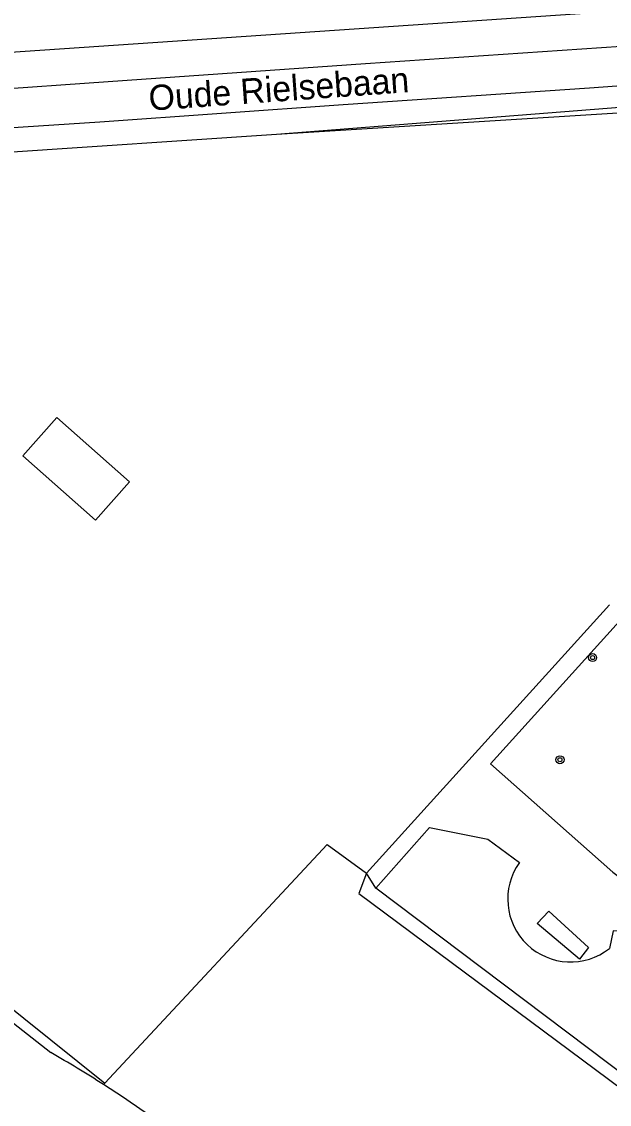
# Model space of a CAD drawing. Extents: x 126000 to 131009, y 393000 to 395500.
# Drawn here: x 130276.9 to 130335, y 394453.7 to 394560.9 of the extents above; entities that cross this region are included whole.
import ezdxf

# ---------------------------------------------------------------- set-up
doc = ezdxf.new("R2010")
doc.units = 0
for name, color, linetype in [('gg-afsc-faunaraster', 7, 'Continuous'), ('gg-anno-openbare ruimte label', 7, 'Continuous'), ('gg-bbg-bijgebouw', 7, 'Continuous'), ('gg-knt-onverhard', 7, 'Continuous'), ('gg-knt-verharding', 7, 'Continuous'), ('gg-kntw-bovenkant insteek waterloop', 7, 'Continuous'), ('gg-kntw-greppel-droge sloot', 7, 'Continuous'), ('gt-grn-groengrens', 7, 'Continuous'), ('gt-grn-groengrens NZ', 7, 'Continuous'), ('gt-grn-vlakafsluiter', 7, 'Continuous'), ('gt-symb-boom', 7, 'Continuous')]:
    doc.layers.add(name, color=color, linetype=linetype)

# ---------------------------------------------------------------- blocks, each defined once
blk = doc.blocks.new('gt0-BOOM')
at = {"layer": 'gt-symb-boom'}
for radius in [0.4, 0.2]:
    blk.add_circle((0, 0), radius, dxfattribs=at)

msp = doc.modelspace()

# ---------------------------------------------------------------- linework, layer by layer
at = {"layer": 'gg-afsc-faunaraster'}
for p, q in [((130378.68, 394554.51), (130302.11, 394549.74)), ((130302.11, 394549.74), (130187.63, 394542.05)), ((130335.05, 394503.16), (130311.01, 394476.57))]:
    msp.add_line(p, q, dxfattribs=at)
for points in [[(130187.63, 394542.05), (130185.82, 394540.52), (130184.79, 394538.46), (130185.47, 394536.26), (130247.98, 394485.55), (130285.09, 394455.78)], [(130285.09, 394455.78), (130307.12, 394479.42), (130311.01, 394476.57)]]:
    msp.add_lwpolyline(points, dxfattribs=at)
at = {"layer": 'gg-bbg-bijgebouw'}
msp.add_lwpolyline([(130280.36, 394521.7), (130276.99, 394517.91), (130284.19, 394511.54), (130287.55, 394515.33), (130280.36, 394521.7)], dxfattribs=at)
at = {"layer": 'gg-knt-onverhard'}
msp.add_lwpolyline([(130279.76, 394458.8), (130246.34, 394485.04), (130229.52, 394498.81), (130213, 394512.65), (130195.84, 394526.59), (130185.5, 394534.84)], dxfattribs=at)
for centre, radius, start, end in [((130220.06, 394354.36), 120.3, 57.3494, 60.2485), ((130219.87, 394354.03), 120.68, 45.3581, 57.3592)]:
    msp.add_arc(centre, radius, start, end, dxfattribs=at)
at = {"layer": 'gg-knt-verharding'}
for points in [[(130424.91, 394564.57), (130411.07, 394563.63), (130385.63, 394561.94), (130361, 394560.25), (130336.23, 394558.45), (130310.9, 394556.74), (130285.45, 394554.95), (130261.04, 394553.24), (130235.64, 394551.46), (130210.72, 394549.8), (130185.37, 394547.93), (130176.1, 394547.26)], [(130427.7, 394560.88), (130404.94, 394559.22), (130380.98, 394557.68), (130357.04, 394556.06), (130333.1, 394554.32), (130308.71, 394552.68), (130284.61, 394550.97), (130273.95, 394550.25), (130249.48, 394548.47), (130223.83, 394546.74), (130199.17, 394544.98), (130191.11, 394544.42)]]:
    msp.add_lwpolyline(points, dxfattribs=at)
at = {"layer": 'gg-kntw-bovenkant insteek waterloop'}
msp.add_lwpolyline([(130175.02, 394550.3), (130211.86, 394553.21), (130237.32, 394555.27), (130331.68, 394561.7), (130367.63, 394564.09), (130399.95, 394565.91), (130419.51, 394567.34), (130427.73, 394568.05), (130430.34, 394568.41), (130431.57, 394568.84)], dxfattribs=at)
at = {"layer": 'gg-kntw-greppel-droge sloot'}
msp.add_lwpolyline([(130381.23, 394554.67), (130381, 394555.93), (130302.11, 394549.74)], dxfattribs=at)
at = {"layer": 'gt-grn-groengrens'}
for points in [[(130336.36, 394501.86), (130323.27, 394487.4), (130335.41, 394476.68), (130347.4, 394467.77)], [(130311.94, 394475.08), (130317.25, 394481.09), (130323.03, 394479.95), (130326.16, 394477.62)], [(130311.01, 394476.57), (130310.25, 394474.58), (130340.24, 394452.24), (130361.68, 394434.98), (130395.12, 394408.67)], [(130395.81, 394409.54), (130362.56, 394436.08), (130341.29, 394452.94), (130311.94, 394475.08)], [(130333, 394469.22), (130332.08, 394468.06), (130327.9, 394471.59), (130329.05, 394472.8), (130333, 394469.22)], [(130347.4, 394467.77), (130339.27, 394470.55), (130335.44, 394470.88), (130335.05, 394469.13)]]:
    msp.add_lwpolyline(points, dxfattribs=at)
msp.add_arc((130331.2, 394474), 6.21, 144.3583, 308.3116, dxfattribs=at)
at = {"layer": 'gt-grn-groengrens NZ'}
msp.add_line((130285.09, 394455.78), (130284.97, 394455.65), dxfattribs=at)
at = {"layer": 'gt-grn-vlakafsluiter'}
msp.add_line((130311.94, 394475.08), (130311.01, 394476.57), dxfattribs=at)

# ---------------------------------------------------------------- block references
at = {"layer": 'gt-symb-boom'}
for p in [(130333.39, 394497.93), (130330.16, 394487.81)]:
    msp.add_blockref('gt0-BOOM', p, dxfattribs=at)

# ---------------------------------------------------------------- texts
at = {"layer": 'gg-anno-openbare ruimte label'}
msp.add_text('Oude Rielsebaan', height=2.5, rotation=4.1, dxfattribs=at).set_placement((130289.53, 394552.09))

doc.saveas('drawing.dxf')
